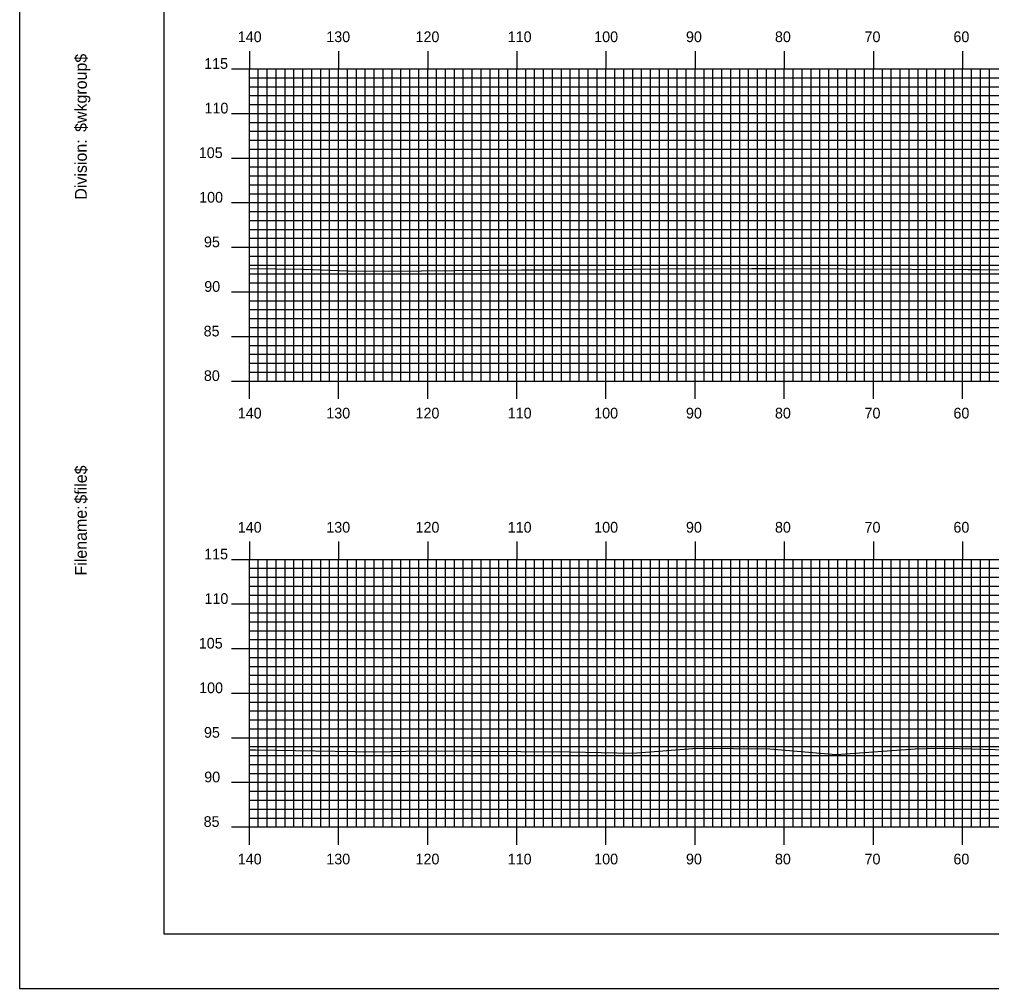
# Model space of a CAD drawing. Extents: x 1761397 to 1761741, y 442591 to 442811.
# Drawn here: x 1761397.5 to 1761506.5, y 442590.5 to 442699.2 of the extents above; entities that cross this region are included whole.
import ezdxf

# ---------------------------------------------------------------- set-up
doc = ezdxf.new("R2010")
doc.units = 0
for name, color, linetype in [('BORDER', 7, 'Continuous'), ('H_V ANNOTATION', 7, 'Continuous'), ('MAJOR', 7, 'Continuous'), ('MINOR', 7, 'Continuous'), ('PLOT BOUNDARY', 7, 'Continuous'), ('S_Roadway_Centerline', 7, 'Continuous')]:
    doc.layers.add(name, color=color, linetype=linetype)

msp = doc.modelspace()

# ---------------------------------------------------------------- linework, layer by layer
at = {"layer": 'BORDER'}
msp.add_lwpolyline([(1761413.64, 442596.67), (1761733.64, 442596.67), (1761733.64, 442806.67), (1761413.64, 442806.67)], close=True, dxfattribs=at)
at = {"layer": 'MAJOR'}
for p, q in [((1761423.24, 442695.67), (1761423.24, 442693.67)), ((1761433.24, 442695.67), (1761433.24, 442693.67)), ((1761443.24, 442695.67), (1761443.24, 442693.67)), ((1761453.24, 442695.67), (1761453.24, 442693.67)), ((1761463.24, 442695.67), (1761463.24, 442693.67)), ((1761473.24, 442695.67), (1761473.24, 442693.67)), ((1761483.24, 442695.67), (1761483.24, 442693.67)), ((1761493.24, 442695.67), (1761493.24, 442693.67)), ((1761503.24, 442695.67), (1761503.24, 442693.67)), ((1761421.24, 442693.67), (1761423.24, 442693.67)), ((1761423.24, 442693.67), (1761703.24, 442693.67)), ((1761423.24, 442658.67), (1761423.24, 442693.67)), ((1761423.24, 442658.67), (1761423.24, 442693.67)), ((1761423.24, 442693.67), (1761703.24, 442693.67)), ((1761433.24, 442658.67), (1761433.24, 442693.67)), ((1761443.24, 442658.67), (1761443.24, 442693.67)), ((1761453.24, 442658.67), (1761453.24, 442693.67)), ((1761463.24, 442658.67), (1761463.24, 442693.67)), ((1761473.24, 442658.67), (1761473.24, 442693.67)), ((1761483.24, 442658.67), (1761483.24, 442693.67)), ((1761493.24, 442658.67), (1761493.24, 442693.67)), ((1761503.24, 442658.67), (1761503.24, 442693.67)), ((1761421.24, 442688.67), (1761423.24, 442688.67)), ((1761423.24, 442688.67), (1761703.24, 442688.67)), ((1761421.24, 442683.67), (1761423.24, 442683.67)), ((1761423.24, 442683.67), (1761703.24, 442683.67)), ((1761421.24, 442678.67), (1761423.24, 442678.67)), ((1761423.24, 442678.67), (1761703.24, 442678.67)), ((1761421.24, 442673.67), (1761423.24, 442673.67)), ((1761423.24, 442673.67), (1761703.24, 442673.67)), ((1761421.24, 442668.67), (1761423.24, 442668.67)), ((1761423.24, 442668.67), (1761703.24, 442668.67)), ((1761421.24, 442663.67), (1761423.24, 442663.67)), ((1761423.24, 442663.67), (1761703.24, 442663.67)), ((1761421.24, 442658.67), (1761423.24, 442658.67)), ((1761423.24, 442658.67), (1761703.24, 442658.67)), ((1761423.24, 442658.67), (1761703.24, 442658.67)), ((1761423.24, 442656.66), (1761423.24, 442658.67)), ((1761433.24, 442656.66), (1761433.24, 442658.67)), ((1761443.24, 442656.66), (1761443.24, 442658.67)), ((1761453.24, 442656.66), (1761453.24, 442658.67)), ((1761463.24, 442656.66), (1761463.24, 442658.67)), ((1761473.24, 442656.66), (1761473.24, 442658.67)), ((1761483.24, 442656.66), (1761483.24, 442658.67)), ((1761493.24, 442656.66), (1761493.24, 442658.67)), ((1761503.24, 442656.66), (1761503.24, 442658.67)), ((1761423.24, 442640.67), (1761423.24, 442638.67)), ((1761433.24, 442640.67), (1761433.24, 442638.67)), ((1761443.24, 442640.67), (1761443.24, 442638.67)), ((1761453.24, 442640.67), (1761453.24, 442638.67)), ((1761463.24, 442640.67), (1761463.24, 442638.67)), ((1761473.24, 442640.67), (1761473.24, 442638.67)), ((1761483.24, 442640.67), (1761483.24, 442638.67)), ((1761493.24, 442640.67), (1761493.24, 442638.67)), ((1761503.24, 442640.67), (1761503.24, 442638.67)), ((1761421.24, 442638.67), (1761423.24, 442638.67)), ((1761423.24, 442638.67), (1761703.24, 442638.67)), ((1761423.24, 442608.67), (1761423.24, 442638.67)), ((1761423.24, 442608.67), (1761423.24, 442638.67)), ((1761423.24, 442638.67), (1761703.24, 442638.67)), ((1761433.24, 442608.67), (1761433.24, 442638.67)), ((1761443.24, 442608.67), (1761443.24, 442638.67)), ((1761453.24, 442608.67), (1761453.24, 442638.67)), ((1761463.24, 442608.67), (1761463.24, 442638.67)), ((1761473.24, 442608.67), (1761473.24, 442638.67)), ((1761483.24, 442608.67), (1761483.24, 442638.67)), ((1761493.24, 442608.67), (1761493.24, 442638.67)), ((1761503.24, 442608.67), (1761503.24, 442638.67)), ((1761421.24, 442633.67), (1761423.24, 442633.67)), ((1761423.24, 442633.67), (1761703.24, 442633.67)), ((1761421.24, 442628.67), (1761423.24, 442628.67)), ((1761423.24, 442628.67), (1761703.24, 442628.67)), ((1761421.24, 442623.67), (1761423.24, 442623.67)), ((1761423.24, 442623.67), (1761703.24, 442623.67)), ((1761421.24, 442618.67), (1761423.24, 442618.67)), ((1761423.24, 442618.67), (1761703.24, 442618.67)), ((1761421.24, 442613.67), (1761423.24, 442613.67)), ((1761423.24, 442613.67), (1761703.24, 442613.67)), ((1761421.24, 442608.67), (1761423.24, 442608.67)), ((1761423.24, 442608.67), (1761703.24, 442608.67)), ((1761423.24, 442608.67), (1761703.24, 442608.67)), ((1761423.24, 442606.66), (1761423.24, 442608.67)), ((1761433.24, 442606.66), (1761433.24, 442608.67)), ((1761443.24, 442606.66), (1761443.24, 442608.67)), ((1761453.24, 442606.66), (1761453.24, 442608.67)), ((1761463.24, 442606.66), (1761463.24, 442608.67)), ((1761473.24, 442606.66), (1761473.24, 442608.67)), ((1761483.24, 442606.66), (1761483.24, 442608.67)), ((1761493.24, 442606.66), (1761493.24, 442608.67)), ((1761503.24, 442606.66), (1761503.24, 442608.67))]:
    msp.add_line(p, q, dxfattribs=at)
at = {"layer": 'MINOR'}
for p, q in [((1761424.24, 442658.67), (1761424.24, 442693.67)), ((1761425.24, 442658.67), (1761425.24, 442693.67)), ((1761426.24, 442658.67), (1761426.24, 442693.67)), ((1761427.24, 442658.67), (1761427.24, 442693.67)), ((1761428.24, 442658.67), (1761428.24, 442693.67)), ((1761429.24, 442658.67), (1761429.24, 442693.67)), ((1761430.24, 442658.67), (1761430.24, 442693.67)), ((1761431.24, 442658.67), (1761431.24, 442693.67)), ((1761432.24, 442658.67), (1761432.24, 442693.67)), ((1761434.24, 442658.67), (1761434.24, 442693.67)), ((1761435.24, 442658.67), (1761435.24, 442693.67)), ((1761436.24, 442658.67), (1761436.24, 442693.67)), ((1761437.24, 442658.67), (1761437.24, 442693.67)), ((1761438.24, 442658.67), (1761438.24, 442693.67)), ((1761439.24, 442658.67), (1761439.24, 442693.67)), ((1761440.24, 442658.67), (1761440.24, 442693.67)), ((1761441.24, 442658.67), (1761441.24, 442693.67)), ((1761442.24, 442658.67), (1761442.24, 442693.67)), ((1761444.24, 442658.67), (1761444.24, 442693.67)), ((1761445.24, 442658.67), (1761445.24, 442693.67)), ((1761446.24, 442658.67), (1761446.24, 442693.67)), ((1761447.24, 442658.67), (1761447.24, 442693.67)), ((1761448.24, 442658.67), (1761448.24, 442693.67)), ((1761449.24, 442658.67), (1761449.24, 442693.67)), ((1761450.24, 442658.67), (1761450.24, 442693.67)), ((1761451.24, 442658.67), (1761451.24, 442693.67)), ((1761452.24, 442658.67), (1761452.24, 442693.67)), ((1761454.24, 442658.67), (1761454.24, 442693.67)), ((1761455.24, 442658.67), (1761455.24, 442693.67)), ((1761456.24, 442658.67), (1761456.24, 442693.67)), ((1761457.24, 442658.67), (1761457.24, 442693.67)), ((1761458.24, 442658.67), (1761458.24, 442693.67)), ((1761459.24, 442658.67), (1761459.24, 442693.67)), ((1761460.24, 442658.67), (1761460.24, 442693.67)), ((1761461.24, 442658.67), (1761461.24, 442693.67)), ((1761462.24, 442658.67), (1761462.24, 442693.67)), ((1761464.24, 442658.67), (1761464.24, 442693.67)), ((1761465.24, 442658.67), (1761465.24, 442693.67)), ((1761466.24, 442658.67), (1761466.24, 442693.67)), ((1761467.24, 442658.67), (1761467.24, 442693.67)), ((1761468.24, 442658.67), (1761468.24, 442693.67)), ((1761469.24, 442658.67), (1761469.24, 442693.67)), ((1761470.24, 442658.67), (1761470.24, 442693.67)), ((1761471.24, 442658.67), (1761471.24, 442693.67)), ((1761472.24, 442658.67), (1761472.24, 442693.67)), ((1761474.24, 442658.67), (1761474.24, 442693.67)), ((1761475.24, 442658.67), (1761475.24, 442693.67)), ((1761476.24, 442658.67), (1761476.24, 442693.67)), ((1761477.24, 442658.67), (1761477.24, 442693.67)), ((1761478.24, 442658.67), (1761478.24, 442693.67)), ((1761479.24, 442658.67), (1761479.24, 442693.67)), ((1761480.24, 442658.67), (1761480.24, 442693.67)), ((1761481.24, 442658.67), (1761481.24, 442693.67)), ((1761482.24, 442658.67), (1761482.24, 442693.67)), ((1761484.24, 442658.67), (1761484.24, 442693.67)), ((1761485.24, 442658.67), (1761485.24, 442693.67)), ((1761486.24, 442658.67), (1761486.24, 442693.67)), ((1761487.24, 442658.67), (1761487.24, 442693.67)), ((1761488.24, 442658.67), (1761488.24, 442693.67)), ((1761489.24, 442658.67), (1761489.24, 442693.67)), ((1761490.24, 442658.67), (1761490.24, 442693.67)), ((1761491.24, 442658.67), (1761491.24, 442693.67)), ((1761492.24, 442658.67), (1761492.24, 442693.67)), ((1761494.24, 442658.67), (1761494.24, 442693.67)), ((1761495.24, 442658.67), (1761495.24, 442693.67)), ((1761496.24, 442658.67), (1761496.24, 442693.67)), ((1761497.24, 442658.67), (1761497.24, 442693.67)), ((1761498.24, 442658.67), (1761498.24, 442693.67)), ((1761499.24, 442658.67), (1761499.24, 442693.67)), ((1761500.24, 442658.67), (1761500.24, 442693.67)), ((1761501.24, 442658.67), (1761501.24, 442693.67)), ((1761502.24, 442658.67), (1761502.24, 442693.67)), ((1761504.24, 442658.67), (1761504.24, 442693.67)), ((1761505.24, 442658.67), (1761505.24, 442693.67)), ((1761506.24, 442658.67), (1761506.24, 442693.67)), ((1761423.24, 442692.67), (1761703.24, 442692.67)), ((1761423.24, 442692.67), (1761425.24, 442692.67)), ((1761423.24, 442691.67), (1761703.24, 442691.67)), ((1761423.24, 442691.67), (1761425.24, 442691.67)), ((1761423.24, 442690.67), (1761703.24, 442690.67)), ((1761423.24, 442690.67), (1761425.24, 442690.67)), ((1761423.24, 442689.67), (1761703.24, 442689.67)), ((1761423.24, 442689.67), (1761425.24, 442689.67)), ((1761423.24, 442687.67), (1761703.24, 442687.67)), ((1761423.24, 442687.67), (1761425.24, 442687.67)), ((1761423.24, 442686.67), (1761703.24, 442686.67)), ((1761423.24, 442686.67), (1761425.24, 442686.67)), ((1761423.24, 442685.67), (1761703.24, 442685.67)), ((1761423.24, 442685.67), (1761425.24, 442685.67)), ((1761423.24, 442684.67), (1761703.24, 442684.67)), ((1761423.24, 442684.67), (1761425.24, 442684.67)), ((1761423.24, 442682.67), (1761703.24, 442682.67)), ((1761423.24, 442682.67), (1761425.24, 442682.67)), ((1761423.24, 442681.67), (1761703.24, 442681.67)), ((1761423.24, 442681.67), (1761425.24, 442681.67)), ((1761423.24, 442680.67), (1761703.24, 442680.67)), ((1761423.24, 442680.67), (1761425.24, 442680.67)), ((1761423.24, 442679.67), (1761703.24, 442679.67)), ((1761423.24, 442679.67), (1761425.24, 442679.67)), ((1761423.24, 442677.67), (1761703.24, 442677.67)), ((1761423.24, 442677.67), (1761425.24, 442677.67)), ((1761423.24, 442676.67), (1761703.24, 442676.67)), ((1761423.24, 442676.67), (1761425.24, 442676.67)), ((1761423.24, 442675.67), (1761703.24, 442675.67)), ((1761423.24, 442675.67), (1761425.24, 442675.67)), ((1761423.24, 442674.67), (1761703.24, 442674.67)), ((1761423.24, 442674.67), (1761425.24, 442674.67)), ((1761423.24, 442672.67), (1761703.24, 442672.67)), ((1761423.24, 442672.67), (1761425.24, 442672.67)), ((1761423.24, 442671.67), (1761703.24, 442671.67)), ((1761423.24, 442671.67), (1761425.24, 442671.67)), ((1761423.24, 442670.67), (1761703.24, 442670.67)), ((1761423.24, 442670.67), (1761425.24, 442670.67)), ((1761423.24, 442669.67), (1761703.24, 442669.67)), ((1761423.24, 442669.67), (1761425.24, 442669.67)), ((1761423.24, 442667.67), (1761703.24, 442667.67)), ((1761423.24, 442667.67), (1761425.24, 442667.67)), ((1761423.24, 442666.67), (1761703.24, 442666.67)), ((1761423.24, 442666.67), (1761425.24, 442666.67)), ((1761423.24, 442665.67), (1761703.24, 442665.67)), ((1761423.24, 442665.67), (1761425.24, 442665.67)), ((1761423.24, 442664.67), (1761703.24, 442664.67)), ((1761423.24, 442664.67), (1761425.24, 442664.67)), ((1761423.24, 442662.67), (1761703.24, 442662.67)), ((1761423.24, 442662.67), (1761425.24, 442662.67)), ((1761423.24, 442661.67), (1761703.24, 442661.67)), ((1761423.24, 442661.67), (1761425.24, 442661.67)), ((1761423.24, 442660.67), (1761703.24, 442660.67)), ((1761423.24, 442660.67), (1761425.24, 442660.67)), ((1761423.24, 442659.67), (1761703.24, 442659.67)), ((1761423.24, 442659.67), (1761425.24, 442659.67)), ((1761424.24, 442608.67), (1761424.24, 442638.67)), ((1761425.24, 442608.67), (1761425.24, 442638.67)), ((1761426.24, 442608.67), (1761426.24, 442638.67)), ((1761427.24, 442608.67), (1761427.24, 442638.67)), ((1761428.24, 442608.67), (1761428.24, 442638.67)), ((1761429.24, 442608.67), (1761429.24, 442638.67)), ((1761430.24, 442608.67), (1761430.24, 442638.67)), ((1761431.24, 442608.67), (1761431.24, 442638.67)), ((1761432.24, 442608.67), (1761432.24, 442638.67)), ((1761434.24, 442608.67), (1761434.24, 442638.67)), ((1761435.24, 442608.67), (1761435.24, 442638.67)), ((1761436.24, 442608.67), (1761436.24, 442638.67)), ((1761437.24, 442608.67), (1761437.24, 442638.67)), ((1761438.24, 442608.67), (1761438.24, 442638.67)), ((1761439.24, 442608.67), (1761439.24, 442638.67)), ((1761440.24, 442608.67), (1761440.24, 442638.67)), ((1761441.24, 442608.67), (1761441.24, 442638.67)), ((1761442.24, 442608.67), (1761442.24, 442638.67)), ((1761444.24, 442608.67), (1761444.24, 442638.67)), ((1761445.24, 442608.67), (1761445.24, 442638.67)), ((1761446.24, 442608.67), (1761446.24, 442638.67)), ((1761447.24, 442608.67), (1761447.24, 442638.67)), ((1761448.24, 442608.67), (1761448.24, 442638.67)), ((1761449.24, 442608.67), (1761449.24, 442638.67)), ((1761450.24, 442608.67), (1761450.24, 442638.67)), ((1761451.24, 442608.67), (1761451.24, 442638.67)), ((1761452.24, 442608.67), (1761452.24, 442638.67)), ((1761454.24, 442608.67), (1761454.24, 442638.67)), ((1761455.24, 442608.67), (1761455.24, 442638.67)), ((1761456.24, 442608.67), (1761456.24, 442638.67)), ((1761457.24, 442608.67), (1761457.24, 442638.67)), ((1761458.24, 442608.67), (1761458.24, 442638.67)), ((1761459.24, 442608.67), (1761459.24, 442638.67)), ((1761460.24, 442608.67), (1761460.24, 442638.67)), ((1761461.24, 442608.67), (1761461.24, 442638.67)), ((1761462.24, 442608.67), (1761462.24, 442638.67)), ((1761464.24, 442608.67), (1761464.24, 442638.67)), ((1761465.24, 442608.67), (1761465.24, 442638.67)), ((1761466.24, 442608.67), (1761466.24, 442638.67)), ((1761467.24, 442608.67), (1761467.24, 442638.67)), ((1761468.24, 442608.67), (1761468.24, 442638.67)), ((1761469.24, 442608.67), (1761469.24, 442638.67)), ((1761470.24, 442608.67), (1761470.24, 442638.67)), ((1761471.24, 442608.67), (1761471.24, 442638.67)), ((1761472.24, 442608.67), (1761472.24, 442638.67)), ((1761474.24, 442608.67), (1761474.24, 442638.67)), ((1761475.24, 442608.67), (1761475.24, 442638.67)), ((1761476.24, 442608.67), (1761476.24, 442638.67)), ((1761477.24, 442608.67), (1761477.24, 442638.67)), ((1761478.24, 442608.67), (1761478.24, 442638.67)), ((1761479.24, 442608.67), (1761479.24, 442638.67)), ((1761480.24, 442608.67), (1761480.24, 442638.67)), ((1761481.24, 442608.67), (1761481.24, 442638.67)), ((1761482.24, 442608.67), (1761482.24, 442638.67)), ((1761484.24, 442608.67), (1761484.24, 442638.67)), ((1761485.24, 442608.67), (1761485.24, 442638.67)), ((1761486.24, 442608.67), (1761486.24, 442638.67)), ((1761487.24, 442608.67), (1761487.24, 442638.67)), ((1761488.24, 442608.67), (1761488.24, 442638.67)), ((1761489.24, 442608.67), (1761489.24, 442638.67)), ((1761490.24, 442608.67), (1761490.24, 442638.67)), ((1761491.24, 442608.67), (1761491.24, 442638.67)), ((1761492.24, 442608.67), (1761492.24, 442638.67)), ((1761494.24, 442608.67), (1761494.24, 442638.67)), ((1761495.24, 442608.67), (1761495.24, 442638.67)), ((1761496.24, 442608.67), (1761496.24, 442638.67)), ((1761497.24, 442608.67), (1761497.24, 442638.67)), ((1761498.24, 442608.67), (1761498.24, 442638.67)), ((1761499.24, 442608.67), (1761499.24, 442638.67)), ((1761500.24, 442608.67), (1761500.24, 442638.67)), ((1761501.24, 442608.67), (1761501.24, 442638.67)), ((1761502.24, 442608.67), (1761502.24, 442638.67)), ((1761504.24, 442608.67), (1761504.24, 442638.67)), ((1761505.24, 442608.67), (1761505.24, 442638.67)), ((1761506.24, 442608.67), (1761506.24, 442638.67)), ((1761423.24, 442637.67), (1761703.24, 442637.67)), ((1761423.24, 442637.67), (1761425.24, 442637.67)), ((1761423.24, 442636.67), (1761703.24, 442636.67)), ((1761423.24, 442636.67), (1761425.24, 442636.67)), ((1761423.24, 442635.67), (1761703.24, 442635.67)), ((1761423.24, 442635.67), (1761425.24, 442635.67)), ((1761423.24, 442634.67), (1761703.24, 442634.67)), ((1761423.24, 442634.67), (1761425.24, 442634.67)), ((1761423.24, 442632.67), (1761703.24, 442632.67)), ((1761423.24, 442632.67), (1761425.24, 442632.67)), ((1761423.24, 442631.67), (1761703.24, 442631.67)), ((1761423.24, 442631.67), (1761425.24, 442631.67)), ((1761423.24, 442630.67), (1761703.24, 442630.67)), ((1761423.24, 442630.67), (1761425.24, 442630.67)), ((1761423.24, 442629.67), (1761703.24, 442629.67)), ((1761423.24, 442629.67), (1761425.24, 442629.67)), ((1761423.24, 442627.67), (1761703.24, 442627.67)), ((1761423.24, 442627.67), (1761425.24, 442627.67)), ((1761423.24, 442626.67), (1761703.24, 442626.67)), ((1761423.24, 442626.67), (1761425.24, 442626.67)), ((1761423.24, 442625.67), (1761703.24, 442625.67)), ((1761423.24, 442625.67), (1761425.24, 442625.67)), ((1761423.24, 442624.67), (1761703.24, 442624.67)), ((1761423.24, 442624.67), (1761425.24, 442624.67)), ((1761423.24, 442622.67), (1761703.24, 442622.67)), ((1761423.24, 442622.67), (1761425.24, 442622.67)), ((1761423.24, 442621.67), (1761703.24, 442621.67)), ((1761423.24, 442621.67), (1761425.24, 442621.67)), ((1761423.24, 442620.67), (1761703.24, 442620.67)), ((1761423.24, 442620.67), (1761425.24, 442620.67)), ((1761423.24, 442619.67), (1761703.24, 442619.67)), ((1761423.24, 442619.67), (1761425.24, 442619.67)), ((1761423.24, 442617.67), (1761703.24, 442617.67)), ((1761423.24, 442617.67), (1761425.24, 442617.67)), ((1761423.24, 442616.67), (1761703.24, 442616.67)), ((1761423.24, 442616.67), (1761425.24, 442616.67)), ((1761423.24, 442615.67), (1761703.24, 442615.67)), ((1761423.24, 442615.67), (1761425.24, 442615.67)), ((1761423.24, 442614.67), (1761703.24, 442614.67)), ((1761423.24, 442614.67), (1761425.24, 442614.67)), ((1761423.24, 442612.67), (1761703.24, 442612.67)), ((1761423.24, 442612.67), (1761425.24, 442612.67)), ((1761423.24, 442611.67), (1761703.24, 442611.67)), ((1761423.24, 442611.67), (1761425.24, 442611.67)), ((1761423.24, 442610.67), (1761703.24, 442610.67)), ((1761423.24, 442610.67), (1761425.24, 442610.67)), ((1761423.24, 442609.67), (1761703.24, 442609.67)), ((1761423.24, 442609.67), (1761425.24, 442609.67))]:
    msp.add_line(p, q, dxfattribs=at)
at = {"layer": 'PLOT BOUNDARY'}
msp.add_lwpolyline([(1761397.45, 442590.55), (1761737.45, 442590.55), (1761737.45, 442810.55), (1761397.45, 442810.55)], close=True, dxfattribs=at)
at = {"layer": 'S_Roadway_Centerline'}
for points in [[(1761423.24, 442671.28), (1761429.31, 442671.21), (1761434.33, 442671.02), (1761438.81, 442670.99), (1761453.76, 442671.15), (1761456.8, 442671.14), (1761460.28, 442671.13), (1761469.27, 442671.23), (1761479.6, 442671.28), (1761482.27, 442671.3), (1761497.56, 442671.22), (1761503.88, 442671.16), (1761505.08, 442671.17), (1761525.57, 442671.03)], [(1761423.24, 442617.33), (1761423.92, 442617.32), (1761437.35, 442617.09), (1761442.51, 442617.2), (1761448.18, 442617.17), (1761459.2, 442617.1), (1761466.23, 442616.93), (1761473.46, 442617.49), (1761481.63, 442617.41), (1761489.07, 442616.8), (1761497.92, 442617.42), (1761500.64, 442617.51), (1761502.88, 442617.47), (1761522.82, 442616.92)]]:
    msp.add_lwpolyline(points, dxfattribs=at)

# ---------------------------------------------------------------- texts
at = {"layer": 'BORDER'}
for s, p in [('$wkgroup$', (1761405.01, 442686.6)), ('Division:', (1761405.01, 442679)), ('$file$', (1761405.01, 442644.92)), ('Filename:', (1761405.01, 442636.86))]:
    msp.add_text(s, height=1.339, rotation=90, dxfattribs=at).set_placement(p)
at = {"layer": 'H_V ANNOTATION'}
for s, p in [('140', (1761421.94, 442696.67)), ('130', (1761431.87, 442696.67)), ('120', (1761441.88, 442696.67)), ('110', (1761452.22, 442696.67)), ('100', (1761461.92, 442696.67)), ('90', (1761472.21, 442696.67)), ('80', (1761482.19, 442696.67)), ('70', (1761492.24, 442696.67)), ('60', (1761502.21, 442696.67)), ('115', (1761418.17, 442693.67)), ('110', (1761418.21, 442688.67)), ('105', (1761417.57, 442683.67)), ('100', (1761417.61, 442678.67)), ('95', (1761418.15, 442673.67)), ('90', (1761418.18, 442668.67)), ('85', (1761418.11, 442663.67)), ('80', (1761418.14, 442658.67)), ('140', (1761421.94, 442654.47)), ('130', (1761431.87, 442654.47)), ('120', (1761441.88, 442654.47)), ('110', (1761452.22, 442654.47)), ('100', (1761461.92, 442654.47)), ('90', (1761472.21, 442654.47)), ('80', (1761482.19, 442654.47)), ('70', (1761492.24, 442654.47)), ('60', (1761502.21, 442654.47)), ('140', (1761421.94, 442641.67)), ('130', (1761431.87, 442641.67)), ('120', (1761441.88, 442641.67)), ('110', (1761452.22, 442641.67)), ('100', (1761461.92, 442641.67)), ('90', (1761472.21, 442641.67)), ('80', (1761482.19, 442641.67)), ('70', (1761492.24, 442641.67)), ('60', (1761502.21, 442641.67)), ('115', (1761418.17, 442638.67)), ('110', (1761418.21, 442633.67)), ('105', (1761417.57, 442628.67)), ('100', (1761417.61, 442623.67)), ('95', (1761418.15, 442618.67)), ('90', (1761418.18, 442613.67)), ('85', (1761418.11, 442608.67)), ('140', (1761421.94, 442604.47)), ('130', (1761431.87, 442604.47)), ('120', (1761441.88, 442604.47)), ('110', (1761452.22, 442604.47)), ('100', (1761461.92, 442604.47)), ('90', (1761472.21, 442604.47)), ('80', (1761482.19, 442604.47)), ('70', (1761492.24, 442604.47)), ('60', (1761502.21, 442604.47))]:
    msp.add_text(s, height=1.2, dxfattribs=at).set_placement(p)
at = {"layer": 'MAJOR'}
for p in [(1761423.23, 442658.67), (1761423.23, 442608.67)]:
    msp.add_text('-', height=0.012, dxfattribs=at).set_placement(p)

doc.saveas('drawing.dxf')
